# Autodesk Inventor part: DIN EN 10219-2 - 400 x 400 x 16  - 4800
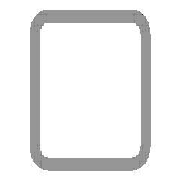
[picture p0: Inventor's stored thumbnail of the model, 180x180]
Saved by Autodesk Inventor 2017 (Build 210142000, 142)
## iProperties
IsCustomPart: 1
Created: 2017-11
Part Number: DIN EN 10219-2 - 400 x 400 x 16  - 4800
Material: Steel, Mild
Description: Cold formed welded structural hollow sections of non-alloy and fine grain structural steel
Document SubType Name: Modeling
Standard: DIN
Designer: iusti
Standard Revision: 2006-07
Standards Organization: DIN
Language: en-US
Size Designation: 400 x 400 x 16
Categories: <MemberInstance><Categories><Category DisplayName="Structural Shapes" InternalName="089c4875-fa83-4c05-b084-43b9cc11f5ed" Mnemonic="GRDR"><CategoryParameter Dis
Stock Number: 400 x 400 x 16
Density: 7.85 g/cm^3
Appearance: Semi-Polished
Mass: 884622 g
Surface Area: 141333 cm^2
Volume: 112691 cm^3
_CCFamilyMember: 142
_CCFamilyDisplayName: DIN EN 10219-2 (Square Hollow Section - Cold Formed) - Cold formed welded structural hollow sections of non-alloy and fine grain structural steel
_FrameMemberDoc: Frame Member File
_Version: 15.0.0
_GetPNFromCC: 1
G_L: 4800.000 mm
G_W: 400.000 mm
G_H: 400.000 mm
+9097C832-944A-4210-ACA6-A5D58FB62A7C+CUTDETAIL1: Cut
Author: iusti
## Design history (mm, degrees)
node "Start plane"
node "End plane"
sketch "Sketch"
  geometry: L1 (-200, -152)-(-200, 152); L2 (-152, 200)-(152, 200); L3 (200, 152)-(200, -152); L4 (152, -200)-(-152, -200); L5 (-152, 184)-(152, 184); L6 (184, 152)-(184, -152); L7 (152, -184)-(-152, -184); L8 (-184, -152)-(-184, 152); L9 (0, 293.918)-(0, -293.918) reference; L10 (-293.918, 0)-(293.918, 0) reference; A1 r 48 centre (-152, -152) between (-200, -152) and (-152, -200); A2 r 48 centre (-152, 152) between (-152, 200) and (-200, 152); A3 r 48 centre (152, 152) between (200, 152) and (152, 200); A4 r 48 centre (152, -152) between (152, -200) and (200, -152); A5 r 32 centre (-152, 152) between (-152, 184) and (-184, 152); A6 r 32 centre (152, 152) between (184, 152) and (152, 184); A7 r 32 centre (152, -152) between (152, -184) and (184, -152); A8 r 32 centre (-152, -152) between (-184, -152) and (-152, -184)
  constraints: 16 end point, 16 point on circle, 8 centre point, 8 tangent, 4 parallel, 3 equal radius, 2 perpendicular, 7 other
  dimensions: "d7" = 48 radius of A1 (= G_IR); "d10" = 400 distance between parallel lines of L2 L4 (= G_H); "d11" = 400 distance between parallel lines of L1 L3 (= G_W); "d12" = 16 distance between parallel lines of L3 L6 (= G_T); "d15" = 200 distance between parallel lines of L2 L10 (= 0.5 x d10); "d16" = 200 distance between parallel lines of L9 L3 (= 0.5 x d11)
extrude "Body" new body sketch "Sketch" stored distance "d3" = 4800 (= G_L); taper "d4" = 0 deg
node "Driven Length"
  sketch "Sketch3"
    geometry: L1 (0, 0)-(10, 0) reference
    constraints: 2 end point, 1 horizontal
  workplane "Work Plane3"
  sketch "Sketch4"
    geometry: L1 (-2, 200)-(12, 200) reference; L2 (-2, 5000)-(12, 5000) reference
    dimensions: "d18" = 4800 distance between parallel lines of L1 L2 (derived)
workplane "Work Plane4"
split "Split1"
body "Solid1"
other parameters: "G_W" = 400 [user parameter; used in 1 equation term], "G_H" = 400 [user parameter; used in 1 equation term], "G_T" = 16 [user parameter; used in 1 equation term], "G_IR" = 48 [user parameter; used in 1 equation term], "G_L" = 4800 (= d18) [user parameter; used in 1 equation term], "G_OFFSET_END" = 0 [user parameter; used in 1 equation term], "d17" = 90 deg
